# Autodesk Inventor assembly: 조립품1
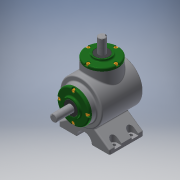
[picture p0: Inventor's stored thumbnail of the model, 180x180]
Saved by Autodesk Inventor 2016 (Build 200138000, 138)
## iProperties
Created: 2017-04
Part Number: 조립품1
Material: 일반
Document SubType Name: Assembly
Designer: USER
Author: USER
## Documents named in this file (15)
- C:\Users\USER\Desktop\470407V1017\조립품1.iam
- C:\Users\USER\Desktop\470407V1017\본체.ipt
- C:\Users\USER\Desktop\470407V1017\메인 베벨기어.ipt
- C:\Users\USER\Desktop\470407V1017\메인 축.ipt
- 메인 축.ipt
- C:\Users\USER\Desktop\470407V1017\베어링 6203.ipt
- C:\Users\USER\Desktop\470407V1017\서브 축.ipt
- 서브 축.ipt
- C:\Users\USER\Desktop\470407V1017\오일실 17 32 8.ipt
- C:\Users\USER\Desktop\470407V1017\커버.ipt
- C:\Users\USER\Desktop\470407V1017\키 4x4.ipt
- C:\Users\USER\Desktop\470407V1017\키 5x5.ipt
- C:\Users\USER\Desktop\470407V1017\서브 베벨기어.ipt
- C:\Users\USER\Desktop\470407V1017\부품1.0001.ipt
- C:\Users\USER\Desktop\470407V1017\볼트 M4.ipt
